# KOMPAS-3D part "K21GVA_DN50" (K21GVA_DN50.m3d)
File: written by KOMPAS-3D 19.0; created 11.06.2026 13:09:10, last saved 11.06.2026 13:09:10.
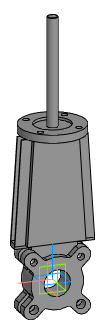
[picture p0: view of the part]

Document properties: Автор: Энергия; Полное имя файла: Z:\3.Личные\kachalov\001_3d для проектировщиков\2.5 Тип_K21GVA. Задвижка\_stp\_stp_K21GVA_DN50-DN1000_с фланцем\K21GVA_DN50.m3d

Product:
- Part/product: K21GVA_DN50

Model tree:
1. Операция без истории:1  (labels: K21GVA_DN50)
